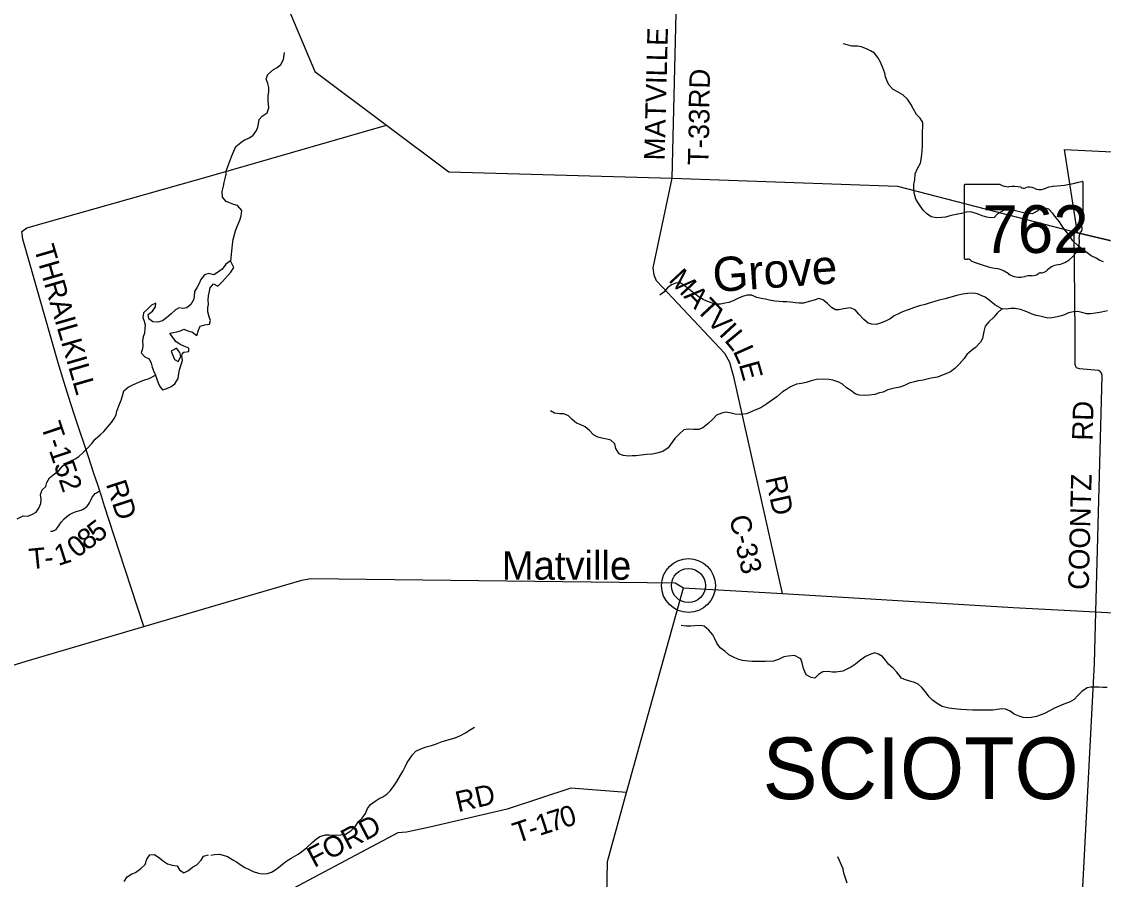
# Model space of a CAD drawing. Extents: x 1643459 to 2064572, y 425441 to 780708.
# Drawn here: x 1790021 to 1805814, y 638720 to 651234 of the extents above; entities that cross this region are included whole.
import ezdxf

# ---------------------------------------------------------------- set-up
doc = ezdxf.new("R2010")
doc.units = 0
for name, color, linetype in [('GE_P_Alignment_100_Curve_Data', 7, 'Continuous'), ('GM_X_Adjacent_County_Text', 7, 'Continuous'), ('GM_X_Interchange_Ramps', 7, 'Continuous'), ('GM_X_Major_River', 7, 'Continuous'), ('GM_X_Major_River_Text', 7, 'Continuous'), ('GM_X_Minor_Lake', 7, 'Continuous'), ('GM_X_Rail_Line', 7, 'Continuous'), ('GM_X_Rail_Line_Text', 7, 'Continuous'), ('GM_X_Section_Text', 7, 'Continuous'), ('GM_X_Township_ROW', 7, 'Continuous'), ('GM_X_Township_Subdivision_Text', 7, 'Continuous'), ('GM_X_US_Route', 7, 'Continuous'), ('PM_P_Cells', 7, 'Continuous'), ('RD_X_Text', 7, 'Continuous'), ('ST_Details', 7, 'Continuous')]:
    doc.layers.add(name, color=color, linetype=linetype)

msp = doc.modelspace()

# ---------------------------------------------------------------- linework, layer by layer
at = {"layer": 'GE_P_Alignment_100_Curve_Data'}
for radius in [393, 249]:
    msp.add_circle((1799756, 643006), radius, dxfattribs=at)
at = {"layer": 'GM_X_Major_River_Text'}
for points in [[(1799517, 648951), (1799582, 651562), (1799611, 651712), (1799644, 651840), (1799828, 652557), (1799859, 652759), (1799823, 652933), (1799388, 654661), (1799392, 654749), (1799404, 654815)], [(1791803, 642410), (1791443, 643510), (1791231, 644167), (1791187, 644312), (1791164, 644382), (1791163, 644385), (1791132, 644477), (1791077, 644641), (1790995, 644886), (1790805, 645462), (1790740, 645658), (1790637, 645983), (1790553, 646258), (1790041, 648058), (1790023, 648174), (1790095, 648228), (1792834, 648999), (1795347, 649725)], [(1805706, 642624), (1805790, 645881), (1805795, 646072), (1805785, 646106), (1805770, 646124), (1805744, 646143), (1805463, 646166), (1805421, 646182), (1805412, 646200), (1805404, 646231), (1805401, 646304), (1805404, 646690), (1805386, 648165)], [(1790443, 643798), (1790478, 643801), (1790523, 643825), (1790567, 643885), (1790602, 643935), (1790641, 643981), (1790680, 644015), (1790719, 644041), (1790758, 644061), (1790818, 644085), (1790889, 644108), (1790920, 644120), (1790948, 644138), (1790978, 644165), (1790996, 644190), (1791010, 644212), (1791032, 644254), (1791053, 644295), (1791074, 644326), (1791097, 644347), (1791114, 644361), (1791127, 644369), (1791145, 644378), (1791163, 644385)], [(1805369, 635815), (1805684, 641868), (1805706, 642624)], [(1798853, 639986), (1798040, 640052), (1797110, 639744), (1795980, 639480), (1795638, 639406), (1795515, 639396), (1793674, 638421), (1793674, 638421)]]:
    msp.add_lwpolyline(points, dxfattribs=at)
at = {"layer": 'GM_X_Minor_Lake'}
for points in [[(1801129, 642890), (1800418, 646052), (1800388, 646154), (1800359, 646263), (1800287, 646392), (1799375, 647365), (1799290, 647454), (1799257, 647533), (1799240, 647643), (1799517, 648951)], [(1786326, 639217), (1786414, 640501), (1786496, 640697), (1786624, 640783), (1788654, 641456), (1789329, 641671), (1790088, 641902), (1791803, 642410), (1793012, 642763), (1794110, 643084), (1794240, 643107), (1799563, 643047), (1799682, 642973)], [(1798632, 631764), (1798625, 631871), (1798519, 633684), (1798508, 634315), (1798542, 636232), (1798557, 637947), (1798574, 638978), (1798853, 639986), (1799682, 642973)], [(1799682, 642973), (1799682, 642973), (1801129, 642890), (1804498, 642688), (1805706, 642624), (1807468, 642522), (1807583, 642525), (1807639, 642541), (1807714, 642573), (1807820, 642626), (1808163, 642799), (1808458, 642943)]]:
    msp.add_lwpolyline(points, dxfattribs=at)
at = {"layer": 'GM_X_Rail_Line'}
msp.add_line((1799756, 643006), (1799756, 643006), dxfattribs=at)
at = {"layer": 'GM_X_Rail_Line_Text'}
msp.add_lwpolyline([(1805906, 648040), (1805436, 648153), (1805248, 649370), (1805941, 649335)], dxfattribs=at)
at = {"layer": 'GM_X_Township_Subdivision_Text'}
for points in [[(1793071, 647746), (1793003, 647695), (1792948, 647624), (1792882, 647575), (1792827, 647539)], [(1793074, 647581), (1793121, 647648), (1793071, 647746)], [(1792827, 647539), (1792755, 647557), (1792689, 647539), (1792637, 647471), (1792611, 647413), (1792586, 647361), (1792544, 647297), (1792538, 647225), (1792529, 647173), (1792489, 647107), (1792435, 647056), (1792373, 647050), (1792323, 647060), (1792267, 647030), (1792202, 646973), (1792136, 646911), (1792080, 646867), (1792008, 646851), (1791937, 646852), (1791878, 646900), (1791870, 646962), (1791930, 647012), (1791976, 647074), (1791979, 647126), (1791919, 647098), (1791858, 647040), (1791798, 646985), (1791792, 646919), (1791809, 646866), (1791823, 646812), (1791821, 646756), (1791817, 646688), (1791796, 646634), (1791788, 646574), (1791792, 646516), (1791788, 646462), (1791765, 646400), (1791819, 646344), (1791881, 646316), (1791911, 646249), (1791925, 646195), (1791950, 646129), (1791974, 646075), (1791994, 646019), (1792016, 645966), (1792038, 645912), (1792079, 645860), (1792129, 645876), (1792202, 645910), (1792256, 645949), (1792306, 646029), (1792317, 646099), (1792327, 646153), (1792345, 646217), (1792371, 646291), (1792360, 646355), (1792371, 646398), (1792390, 646413), (1792462, 646419), (1792464, 646469), (1792412, 646487), (1792344, 646518), (1792275, 646562), (1792227, 646624), (1792185, 646688), (1792235, 646700), (1792285, 646706), (1792339, 646724), (1792389, 646746), (1792449, 646721), (1792517, 646701), (1792581, 646657), (1792602, 646731), (1792626, 646792), (1792694, 646810), (1792762, 646818), (1792778, 646872), (1792761, 646928), (1792739, 647000), (1792739, 647058), (1792747, 647114), (1792746, 647168), (1792750, 647234), (1792764, 647300), (1792772, 647352), (1792824, 647408)], [(1792824, 647408), (1792886, 647375), (1792955, 647442), (1793074, 647581)], [(1792234, 646352), (1792251, 646306), (1792307, 646275), (1792346, 646349), (1792332, 646407), (1792282, 646470), (1792206, 646424)], [(1792206, 646424), (1792234, 646352)]]:
    msp.add_lwpolyline(points, dxfattribs=at)
at = {"layer": 'GM_X_US_Route'}
for points in [[(1802414, 650809), (1802364, 650830), (1802282, 650864), (1802222, 650877), (1802144, 650876), (1802072, 650896), (1802016, 650911)], [(1793073, 647741), (1793098, 647984), (1793110, 648057), (1793127, 648129), (1793143, 648181), (1793166, 648246), (1793205, 648338), (1793226, 648403), (1793234, 648477), (1793173, 648549), (1793119, 648568), (1793069, 648586), (1793007, 648611), (1792956, 648675), (1792949, 648755), (1792967, 648835), (1792976, 648885), (1792992, 648946), (1793009, 649010), (1793014, 649066), (1793038, 649133), (1793063, 649197), (1793092, 649274), (1793118, 649346), (1793149, 649412), (1793223, 649473), (1793276, 649510), (1793336, 649532), (1793401, 649579), (1793449, 649644), (1793470, 649694), (1793480, 649744), (1793489, 649805), (1793535, 649855), (1793604, 649902), (1793632, 649976), (1793621, 650085), (1793618, 650145), (1793629, 650213), (1793629, 650271), (1793614, 650331), (1793592, 650401), (1793615, 650465), (1793698, 650538), (1793750, 650563), (1793804, 650608), (1793845, 650684), (1793860, 650785)], [(1805818, 647730), (1805760, 647749), (1805708, 647785), (1805636, 647818), (1805575, 647860), (1805505, 647915), (1805443, 647967), (1805366, 648038), (1805317, 648108), (1805271, 648172), (1805222, 648235), (1805171, 648311), (1805123, 648373), (1805078, 648434), (1805016, 648496), (1804966, 648514), (1804912, 648527), (1804856, 648474), (1804775, 648431), (1804713, 648435), (1804647, 648446), (1804568, 648466), (1804490, 648481), (1804420, 648482), (1804364, 648482), (1804269, 648431), (1804221, 648378), (1804166, 648371), (1804112, 648379), (1804045, 648402), (1803985, 648426), (1803879, 648461), (1803809, 648454), (1803743, 648436), (1803687, 648425), (1803614, 648410), (1803560, 648394), (1803508, 648381), (1803456, 648375), (1803380, 648372), (1803302, 648385), (1803232, 648433), (1803181, 648484), (1803118, 648574), (1803076, 648642), (1803053, 648734), (1803046, 648792), (1803046, 648856), (1803059, 648926), (1803066, 649015), (1803098, 649091), (1803143, 649170), (1803152, 649224), (1803164, 649296), (1803169, 649354), (1803171, 649410), (1803172, 649483), (1803171, 649551), (1803175, 649627), (1803176, 649703), (1803177, 649763), (1803139, 649825), (1803088, 649879), (1803042, 649957), (1803001, 650028), (1802952, 650102), (1802888, 650168), (1802820, 650205), (1802747, 650244), (1802683, 650310), (1802658, 650364), (1802634, 650430), (1802621, 650482), (1802594, 650560), (1802562, 650642), (1802521, 650713), (1802471, 650773), (1802414, 650809)], [(1803214, 647109), (1803130, 647086), (1803044, 647060), (1802963, 647031), (1802883, 647002), (1802821, 646973), (1802760, 646941), (1802700, 646898), (1802642, 646867), (1802561, 646836), (1802495, 646814), (1802433, 646821), (1802381, 646835), (1802318, 646888), (1802244, 646966), (1802189, 647029), (1802117, 647057), (1802021, 647044), (1801957, 647031), (1801905, 647029), (1801847, 647064), (1801785, 647120), (1801720, 647175), (1801662, 647193), (1801590, 647172), (1801519, 647149), (1801437, 647126), (1801373, 647126), (1801319, 647131), (1801247, 647140), (1801195, 647144), (1801141, 647147), (1801081, 647151), (1801017, 647156), (1800941, 647172), (1800879, 647187), (1800817, 647194), (1800753, 647210), (1800678, 647241), (1800612, 647243), (1800543, 647224), (1800487, 647197), (1800409, 647159), (1800347, 647138), (1800290, 647127), (1800226, 647113), (1800148, 647114), (1800092, 647129), (1800023, 647155), (1799969, 647182), (1799915, 647216), (1799849, 647261), (1799786, 647313), (1799714, 647370), (1799647, 647420), (1799583, 647421), (1799510, 647396), (1799452, 647350), (1799395, 647287), (1799339, 647242)], [(1805875, 647013), (1805785, 646996), (1805701, 646981), (1805628, 646970), (1805574, 646970), (1805499, 646989), (1805439, 647004), (1805377, 647002), (1805306, 646985), (1805246, 646956), (1805184, 646936), (1805116, 646923), (1805060, 646914), (1805003, 646910), (1804946, 646921), (1804888, 646935), (1804832, 646948), (1804774, 646966), (1804720, 646989), (1804656, 647015), (1804604, 647034), (1804528, 647050), (1804464, 647051), (1804394, 647040), (1804332, 647044), (1804227, 647101), (1804149, 647172), (1804086, 647216), (1804028, 647239), (1803976, 647261), (1803916, 647270), (1803836, 647268), (1803758, 647259), (1803676, 647240), (1803587, 647215), (1803505, 647192), (1803415, 647169), (1803353, 647149), (1803284, 647130), (1803214, 647109)], [(1804343, 647043), (1804322, 647036), (1804262, 646981), (1804213, 646922), (1804144, 646854), (1804090, 646791), (1804069, 646712), (1804059, 646662), (1804050, 646610), (1804020, 646558), (1803949, 646479), (1803890, 646434), (1803820, 646377), (1803783, 646317), (1803710, 646238), (1803646, 646173), (1803583, 646126), (1803515, 646094), (1803449, 646069), (1803390, 646048), (1803300, 646031), (1803240, 646019), (1803184, 646002), (1803110, 645992), (1803058, 645979), (1802981, 645958), (1802909, 645923), (1802843, 645899), (1802765, 645886), (1802666, 645861), (1802598, 645830), (1802546, 645818), (1802478, 645795), (1802397, 645782), (1802325, 645780), (1802249, 645785), (1802191, 645806), (1802126, 645852), (1802064, 645891), (1802005, 645943), (1801953, 645974), (1801865, 646002), (1801813, 646011), (1801713, 646016), (1801625, 646013), (1801547, 645993), (1801477, 645970), (1801408, 645955), (1801336, 645944), (1801248, 645908), (1801187, 645867), (1801131, 645834), (1801046, 645761), (1800899, 645656), (1800811, 645601), (1800724, 645564), (1800672, 645541), (1800602, 645512), (1800510, 645501), (1800440, 645509), (1800362, 645528), (1800304, 645534), (1800244, 645521), (1800167, 645492), (1800117, 645438), (1800038, 645365), (1799967, 645308), (1799909, 645285), (1799835, 645284), (1799759, 645286), (1799691, 645279), (1799626, 645222), (1799558, 645151), (1799519, 645097), (1799460, 645014), (1799384, 644963), (1799296, 644936), (1799233, 644922), (1799143, 644917), (1799067, 644908), (1798993, 644901), (1798937, 644897), (1798885, 644892), (1798805, 644904), (1798747, 644929), (1798694, 645005), (1798680, 645075), (1798621, 645126), (1798565, 645140), (1798509, 645151), (1798433, 645171), (1798369, 645206), (1798310, 645270), (1798248, 645323), (1798177, 645355), (1798123, 645374), (1798057, 645430), (1798006, 645485), (1797936, 645513), (1797880, 645514), (1797800, 645522)], [(1789957, 643982), (1790042, 644022), (1790114, 644019), (1790180, 644049), (1790232, 644075), (1790272, 644133), (1790301, 644205), (1790307, 644267), (1790297, 644333), (1790323, 644401), (1790374, 644453), (1790390, 644511), (1790426, 644577), (1790477, 644616), (1790565, 644684), (1790623, 644754), (1790677, 644796), (1790732, 644821), (1790804, 644855), (1790854, 644887), (1790918, 644949), (1790987, 645018), (1791045, 645080), (1791097, 645140), (1791168, 645206), (1791220, 645253), (1791274, 645317), (1791335, 645387), (1791373, 645443), (1791403, 645499), (1791413, 645551), (1791440, 645629), (1791474, 645709), (1791496, 645773), (1791515, 645847), (1791577, 645902), (1791645, 645936), (1791740, 645978), (1791806, 646002), (1791884, 646027), (1791974, 646075)], [(1797800, 645522), (1797742, 645555)], [(1799723, 642416), (1799651, 642422)], [(1805868, 641519), (1805808, 641521), (1805746, 641524), (1805630, 641523), (1805578, 641516), (1805500, 641461), (1805439, 641401), (1805386, 641346), (1805320, 641307), (1805262, 641287), (1805202, 641262), (1805101, 641217), (1805039, 641182), (1804952, 641139), (1804892, 641117), (1804836, 641098), (1804758, 641083), (1804704, 641077), (1804642, 641082), (1804584, 641100), (1804510, 641129), (1804454, 641173), (1804384, 641204), (1804333, 641210), (1804262, 641197), (1804200, 641188), (1804130, 641186), (1804060, 641187), (1803994, 641188), (1803910, 641190), (1803814, 641193), (1803734, 641200), (1803636, 641209), (1803558, 641218), (1803458, 641241), (1803385, 641285), (1803321, 641334), (1803271, 641384), (1803216, 641454), (1803163, 641519), (1803109, 641567), (1803057, 641592), (1802975, 641614), (1802925, 641629), (1802866, 641655), (1802798, 641742), (1802745, 641800), (1802679, 641857), (1802634, 641917), (1802590, 641969), (1802529, 642006), (1802477, 642024), (1802417, 642003), (1802340, 641970), (1802252, 641907), (1802193, 641861), (1802137, 641820), (1802086, 641794), (1802012, 641759), (1801910, 641742), (1801858, 641743), (1801790, 641753), (1801720, 641748), (1801657, 641709), (1801599, 641657), (1801547, 641666), (1801475, 641703), (1801438, 641797), (1801417, 641879), (1801399, 641937), (1801306, 641985), (1801214, 641978), (1801147, 641967), (1801069, 641926), (1800999, 641905), (1800881, 641898), (1800819, 641896), (1800736, 641897), (1800686, 641900), (1800634, 641902), (1800543, 641913), (1800477, 641934), (1800413, 641962), (1800345, 641997), (1800286, 642047), (1800220, 642096), (1800173, 642166), (1800141, 642230), (1800114, 642288), (1800056, 642355), (1799985, 642415), (1799929, 642422), (1799849, 642418), (1799789, 642415), (1799723, 642416)], [(1792785, 639072), (1792839, 639084), (1792909, 639085), (1792963, 639074), (1793025, 639054), (1793103, 639003), (1793157, 638973), (1793214, 638938), (1793280, 638894), (1793342, 638863), (1793403, 638833), (1793477, 638812), (1793531, 638802), (1793613, 638805), (1793668, 638826), (1793720, 638856), (1793772, 638891), (1793831, 638942), (1793893, 638992), (1793954, 639029), (1794056, 639088), (1794107, 639123), (1794185, 639184), (1794264, 639258), (1794324, 639313), (1794375, 639344), (1794455, 639369), (1794511, 639369), (1794591, 639366), (1794681, 639367), (1794749, 639381), (1794828, 639428), (1794893, 639497), (1794939, 639562), (1794992, 639612), (1795040, 639679), (1795071, 639751), (1795116, 639814), (1795184, 639861), (1795242, 639899), (1795293, 639924), (1795351, 639963), (1795408, 640015), (1795460, 640090), (1795499, 640146), (1795554, 640241), (1795590, 640304), (1795619, 640362), (1795652, 640425), (1795684, 640475), (1795721, 640530), (1795775, 640588), (1795848, 640623), (1795926, 640652), (1796004, 640675), (1796064, 640691), (1796161, 640730), (1796317, 640776), (1796375, 640794), (1796430, 640817), (1796500, 640856), (1796559, 640898), (1796635, 640939)], [(1791519, 638686), (1791562, 638754), (1791630, 638799), (1791682, 638821), (1791760, 638877), (1791823, 638937), (1791849, 639013), (1791893, 639078), (1791962, 639082), (1792037, 639030), (1792091, 638983), (1792151, 638947), (1792219, 638929), (1792291, 638918), (1792327, 638858), (1792391, 638817), (1792459, 638851), (1792514, 638899), (1792578, 638933), (1792640, 639000), (1792676, 639056), (1792747, 639078)], [(1802072, 638662), (1802042, 638752), (1802023, 638812), (1802015, 638872), (1801992, 638926), (1801963, 638994), (1801937, 639047)]]:
    msp.add_lwpolyline(points, dxfattribs=at)
at = {"layer": 'RD_X_Text'}
for points in [[(1784246, 657416), (1784376, 657379), (1784506, 657343), (1784874, 657325), (1785227, 657309), (1785368, 657303), (1785894, 657223), (1788277, 656990), (1788596, 656986), (1788740, 656956), (1789264, 656595), (1789821, 656200), (1790375, 655803), (1791016, 655344), (1792215, 654458), (1792947, 653623), (1793870, 651535), (1794301, 650507), (1795347, 649725), (1796257, 649043), (1799517, 648951), (1802807, 648835), (1805386, 648165), (1805438, 648152)], [(1805438, 648152), (1805906, 648040), (1806162, 647976)]]:
    msp.add_lwpolyline(points, dxfattribs=at)
at = {"layer": 'ST_Details'}
for p, q in [((1803780, 648842), (1803780, 647785)), ((1804307, 648860), (1803798, 648860)), ((1805521, 648333), (1805521, 648886)), ((1805520, 648333), (1805521, 648333))]:
    msp.add_line(p, q, dxfattribs=at)
for centre, major_axis, start_param, end_param in [((1803800, 648844), (20.2, 0), 1.712693, 3.28349), ((1804429, 648982), (196, 0), 4.042523, 4.731795), ((1804493, 648266), (702, 0), 1.404758, 1.657858), ((1804653, 648849), (56.4, 0), 3.836095, 5.185415), ((1804736, 648727), (117, 0), 0.950623, 2.079405), ((1804887, 648895), (141, 0), 4.081561, 5.145723), ((1805136, 648537), (371, 0), 1.699011, 2.107814), ((1804901, 650300), (1845, 0), 4.814394, 5.042369), ((1805501, 648888), (19.4, 0), 6.141152, 7.989035), ((1805516, 648293), (30, 0), 1.883978, 3.671073), ((1805500, 648331), (20.7, 0), 5.05454, 6.418171), ((1805590, 648102), (131, 0), 2.387724, 3.262537), ((1805325, 648223), (180, 0), 5.934695, 6.695948), ((1805004, 648032), (462, 0), 5.101752, 6.440018), ((1803800, 647783), (20.3, 0), 3.00124, 4.508301), ((1803804, 647891), (155, 0), 4.665946, 4.897461), ((1803835, 647724), (56, 0), 0.519207, 1.627899), ((1804542, 648673), (1333, 0), 4.195997, 4.488961), ((1805199, 647488), (253, 0), 1.647645, 2.488434), ((1804145, 647310), (417, 0), 0.823519, 1.323587), ((1804596, 647719), (265, 0), 4.026481, 4.996735), ((1804748, 647353), (217, 0), 1.495662, 1.94098), ((1804768, 647640), (141, 0), 4.691044, 5.507374), ((1804895, 647537), (39.7, 0), 1.147584, 2.315152), ((1804878, 647682), (149, 0), 4.937069, 5.64225)]:
    msp.add_ellipse(centre, major_axis=major_axis, ratio=0.8, start_param=start_param, end_param=end_param, dxfattribs=at)

# ---------------------------------------------------------------- texts
at = {"layer": 'GM_X_Adjacent_County_Text'}
msp.add_text('SCIOTO', height=900, rotation=0, dxfattribs=at).set_placement((1800839, 639890))
at = {"layer": 'GM_X_Interchange_Ramps'}
msp.add_text('Grove', height=500, rotation=4.1169, dxfattribs=at).set_placement((1800127, 647287))
at = {"layer": 'GM_X_Major_River'}
for s, rotation, p in [('MATVILLE', 88.5211, (1799408, 649206)), ('RD', 88.5175, (1800059, 649964)), ('T-33', 88.5864, (1800046, 649137)), ('THRAILKILL', 286.1481, (1790198, 647932)), ('RD', 88.5194, (1805656, 645118)), ('T-152', 288.5259, (1790297, 645339)), ('RD', 287.9682, (1791249, 644489)), ('COONTZ', 88.4749, (1805599, 642940)), ('5', 37.1076, (1791124, 643619)), ('0', 37.2388, (1790828, 643398)), ('8', 36.3618, (1790973, 643508)), ('T', 5.6291, (1790143, 643243)), ('1', 17.5951, (1790554, 643291)), ('-', 5.6292, (1790366, 643265)), ('RD', 12.9582, (1796393, 639699)), ('0', 16.7611, (1797931, 639465)), ('FORD', 27.7817, (1794292, 638884)), ('1', 18.091, (1797581, 639352)), ('7', 17.7915, (1797756, 639409)), ('T', 18.1964, (1797251, 639244)), ('-', 18.1708, (1797464, 639314))]:
    msp.add_text(s, height=300, rotation=rotation, dxfattribs=at).set_placement(p)
at = {"layer": 'GM_X_Section_Text'}
for s, rotation, p in [('M', 313.0176, (1799454, 647457)), ('A', 313.0162, (1799676, 647219)), ('T', 313.015, (1799856, 647026)), ('V', 313.011, (1800009, 646862)), ('I', 312.7641, (1800189, 646669)), ('L', 309.6102, (1800270, 646582)), ('L', 294.0996, (1800402, 646427)), ('E', 285.5716, (1800489, 646234)), ('RD', 282.4756, (1800877, 644573)), ('C-33', 282.7885, (1800351, 644001))]:
    msp.add_text(s, height=300, rotation=rotation, dxfattribs=at).set_placement(p)
at = {"layer": 'GM_X_Township_ROW'}
msp.add_text('Matville', height=417, rotation=0, dxfattribs=at).set_placement((1797031, 643091))
at = {"layer": 'PM_P_Cells'}
msp.add_text('762', height=1, rotation=0, dxfattribs=at).set_placement((1804278, 648170))
for s in ['s', 'r']:
    msp.add_text(s, height=1, dxfattribs=at).set_placement((1804631, 648243))
at = {"layer": 'ST_Details'}
msp.add_text('762', height=696.1, dxfattribs=at).set_placement((1804046, 647859))

doc.saveas('drawing.dxf')
